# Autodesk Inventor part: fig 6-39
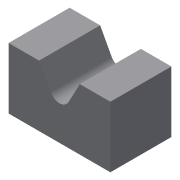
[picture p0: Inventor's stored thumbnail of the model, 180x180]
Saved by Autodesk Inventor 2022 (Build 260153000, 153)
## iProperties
Created: 2005-12
Part Number: fig 6-39
Document SubType Name: Modeling
Designer: CADCIM
Density: 1 g/cm^3
Material: Generic
Appearance: Default
Author: CADCIM
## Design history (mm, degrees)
sketch "Sketch1"
  geometry: L1 (10, 15)-(25, 15); L2 (25, 15)-(25, -15); L3 (25, -15)-(-25, -15); L4 (-25, -15)-(-25, 15); L5 (-25, 15)-(-10, 15); L6 (-10, 15)-(-2, 0); L7 (-2, 0)-(2, 0); L8 (2, 0)-(10, 15); 1 further point
  constraints: 16 end point, 3 equal length, 3 parallel, 1 collinear, 1 horizontal, 1 perpendicular, 1 other
  dimensions: "d0" = 50 distance of L2.end L3.end; "d1" = 25 distance from line of point (0, 0) L2; "d2" = 30 distance of L1.end L2.end; "d3" = 15 distance of L1.start L1.end; "d4" = 15 distance between parallel lines of L1 L7; "d5" = 4 distance of L6.end L7.end; "d6" = 15 distance from line of point (0, 0) L3
extrude "Extrusion1" new body sketch "Sketch1" stored distance "d7" = 30; taper "d8" = 0 deg
fillet "Fillet4" dims "d11" = 5
body "Solid1"
